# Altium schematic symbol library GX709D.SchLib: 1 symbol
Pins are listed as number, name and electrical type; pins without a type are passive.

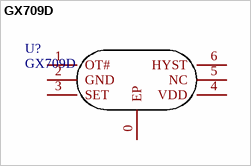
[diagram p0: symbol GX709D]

## GX709D
designator U?
footprint DFN-6-EP_L1.5-W1.5-P0.50-BL
pins: 0 EP, 1 OT#, 2 GND, 3 SET, 4 VDD, 5 NC, 6 HYST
